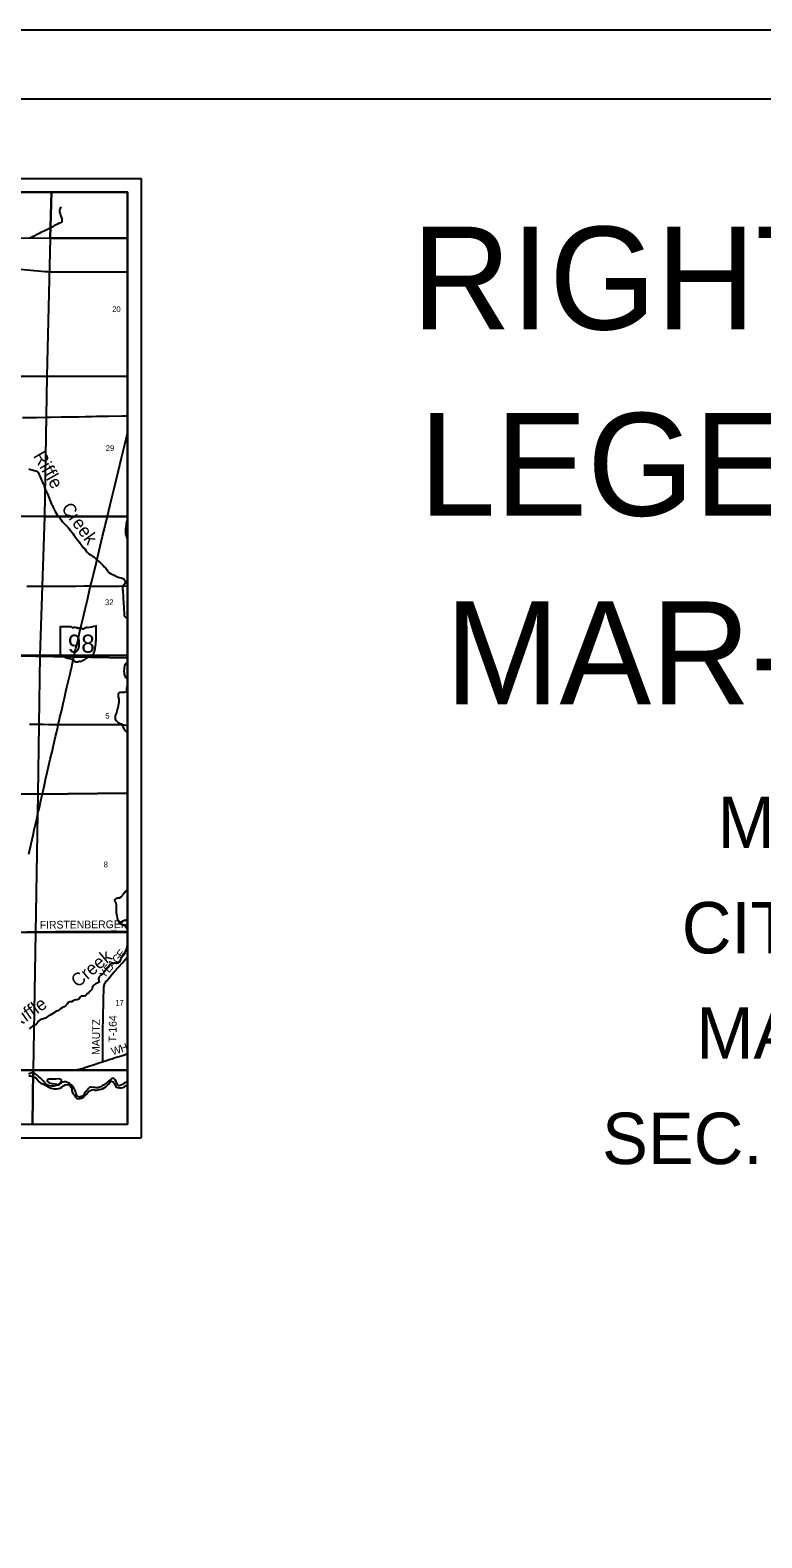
# Model space of a CAD drawing. Extents: x -97 to 34, y -21 to 22.
# Drawn here: x 9.64 to 14.98, y 11 to 22 of the extents above; entities that cross this region are included whole.
import ezdxf

# ---------------------------------------------------------------- set-up
doc = ezdxf.new("R2010")
doc.units = 0
for name, color, linetype in [('GM_X_County_Road', 7, 'Continuous'), ('GM_X_County_Road_Text', 7, 'Continuous'), ('GM_X_Major_River', 7, 'Continuous'), ('GM_X_Minor_River', 7, 'Continuous'), ('GM_X_Minor_River_Text', 7, 'Continuous'), ('GM_X_Section', 7, 'Continuous'), ('GM_X_Section_Text', 7, 'Continuous'), ('GM_X_State_Location', 7, 'Continuous'), ('GM_X_State_Route', 7, 'Continuous'), ('GM_X_State_Shield', 7, 'Continuous'), ('GM_X_Township', 7, 'Continuous'), ('GM_X_Township_Road', 7, 'Continuous'), ('GM_X_Township_Road_Text', 7, 'Continuous'), ('SH_Border', 7, 'Continuous'), ('SH_Cut_Line', 7, 'Continuous'), ('SH_Data', 7, 'Continuous'), ('SH_Text', 7, 'Continuous')]:
    doc.layers.add(name, color=color, linetype=linetype)

msp = doc.modelspace()

# ---------------------------------------------------------------- linework, layer by layer
at = {"layer": 'GM_X_County_Road'}
for points in [[(9.568, 20.257), (9.67, 20.247), (9.701, 20.244), (9.75, 20.24), (9.772, 20.238), (9.791, 20.237), (9.815, 20.237), (9.868, 20.237), (9.94, 20.237), (10.036, 20.237), (10.075, 20.237), (10.089, 20.237), (10.179, 20.237), (10.226, 20.237), (10.263, 20.237), (10.3, 20.237), (10.351, 20.236)], [(9.617, 17.943), (9.658, 17.943), (9.695, 17.943), (9.745, 17.943), (9.814, 17.943), (9.873, 17.944), (9.941, 17.944), (9.975, 17.944), (10.034, 17.945), (10.071, 17.945), (10.083, 17.945)], [(10.083, 17.945), (10.09, 17.944), (10.124, 17.944), (10.174, 17.944), (10.211, 17.944), (10.252, 17.944), (10.292, 17.944), (10.342, 17.945), (10.351, 17.945)], [(9.505, 15.42), (9.508, 15.42), (9.53, 15.42), (9.617, 15.421), (9.654, 15.421), (9.7, 15.421), (9.732, 15.422), (9.825, 15.423), (9.862, 15.423), (9.899, 15.423), (9.958, 15.424), (10.024, 15.424), (10.061, 15.425), (10.092, 15.425), (10.138, 15.425), (10.204, 15.425), (10.232, 15.426), (10.272, 15.426), (10.303, 15.425), (10.34, 15.425), (10.351, 15.425)], [(10.171, 14.474), (10.175, 14.476), (10.199, 14.483), (10.226, 14.492), (10.241, 14.496), (10.255, 14.501), (10.273, 14.506), (10.291, 14.511), (10.324, 14.521), (10.35, 14.531), (10.351, 14.532)], [(9.277, 14.411), (9.359, 14.41), (9.393, 14.409), (9.477, 14.41), (9.517, 14.411), (9.614, 14.411), (9.665, 14.412)], [(9.66, 14.018), (9.66, 14.037), (9.66, 14.062), (9.661, 14.087), (9.662, 14.161), (9.663, 14.192), (9.663, 14.22), (9.665, 14.257), (9.665, 14.269), (9.665, 14.285), (9.664, 14.32), (9.665, 14.354), (9.664, 14.362), (9.664, 14.367), (9.664, 14.369), (9.665, 14.377), (9.665, 14.387), (9.665, 14.397), (9.665, 14.408), (9.665, 14.412)], [(9.665, 14.412), (9.676, 14.412), (9.722, 14.412), (9.785, 14.413)], [(9.785, 14.413), (9.788, 14.413), (9.859, 14.413), (9.878, 14.414), (9.899, 14.414), (9.93, 14.415), (9.966, 14.415)], [(9.966, 14.415), (9.984, 14.417), (9.996, 14.418), (10.002, 14.419), (10.009, 14.421), (10.016, 14.423), (10.028, 14.426), (10.049, 14.433), (10.078, 14.443), (10.105, 14.452), (10.143, 14.465), (10.171, 14.474)]]:
    msp.add_lwpolyline(points, dxfattribs=at)
at = {"layer": 'GM_X_Major_River'}
for points in [[(9.841, 14.302), (9.824, 14.298), (9.812, 14.295), (9.799, 14.295), (9.786, 14.297), (9.776, 14.3), (9.764, 14.306), (9.75, 14.319), (9.737, 14.335), (9.726, 14.345), (9.716, 14.356), (9.705, 14.364), (9.692, 14.376), (9.678, 14.385), (9.668, 14.391), (9.655, 14.393), (9.643, 14.389), (9.629, 14.383)], [(9.632, 14.371), (9.645, 14.372), (9.66, 14.367), (9.673, 14.362), (9.685, 14.354), (9.696, 14.341), (9.708, 14.326), (9.721, 14.317), (9.735, 14.312), (9.748, 14.304), (9.76, 14.297), (9.771, 14.291), (9.782, 14.286), (9.796, 14.281), (9.806, 14.279), (9.816, 14.277), (9.837, 14.277), (9.852, 14.279), (9.861, 14.282), (9.874, 14.289), (9.884, 14.298), (9.897, 14.305), (9.91, 14.307), (9.923, 14.306), (9.935, 14.299), (9.942, 14.286), (9.945, 14.276), (9.946, 14.265), (9.948, 14.254), (9.954, 14.241), (9.963, 14.231), (9.972, 14.216), (9.982, 14.206), (9.995, 14.204), (10.006, 14.206), (10.017, 14.209), (10.031, 14.216), (10.043, 14.227), (10.052, 14.238), (10.062, 14.25), (10.071, 14.258), (10.081, 14.265), (10.092, 14.269), (10.103, 14.27), (10.116, 14.267), (10.126, 14.266), (10.138, 14.268), (10.148, 14.27), (10.16, 14.274), (10.17, 14.277), (10.183, 14.284), (10.193, 14.291), (10.206, 14.302), (10.218, 14.313), (10.225, 14.326), (10.235, 14.333), (10.247, 14.327), (10.256, 14.317), (10.262, 14.304), (10.267, 14.29), (10.28, 14.285), (10.293, 14.284), (10.306, 14.284), (10.319, 14.286), (10.331, 14.291), (10.343, 14.3), (10.351, 14.305)], [(9.851, 14.306), (9.851, 14.307), (9.852, 14.312), (9.856, 14.316), (9.863, 14.322), (9.867, 14.325), (9.871, 14.331), (9.871, 14.341), (9.863, 14.347), (9.848, 14.348), (9.83, 14.346), (9.81, 14.347), (9.792, 14.346), (9.777, 14.346), (9.768, 14.345), (9.766, 14.331), (9.781, 14.32), (9.801, 14.316), (9.823, 14.312), (9.834, 14.31), (9.839, 14.306), (9.841, 14.302)], [(9.841, 14.302), (9.851, 14.306)], [(9.851, 14.306), (9.841, 14.302)], [(10.351, 14.333), (10.344, 14.325), (10.328, 14.318), (10.316, 14.308), (10.303, 14.302), (10.292, 14.299), (10.282, 14.305), (10.276, 14.315), (10.27, 14.329), (10.262, 14.342), (10.251, 14.354), (10.238, 14.352), (10.226, 14.342), (10.213, 14.331), (10.203, 14.322), (10.178, 14.303), (10.167, 14.298), (10.157, 14.291), (10.147, 14.288), (10.137, 14.284), (10.124, 14.284), (10.113, 14.285), (10.088, 14.289), (10.077, 14.289), (10.067, 14.278), (10.061, 14.268), (10.051, 14.259), (10.038, 14.245), (10.033, 14.232), (10.023, 14.222), (10.013, 14.22), (10, 14.216), (9.987, 14.22), (9.982, 14.23), (9.978, 14.24), (9.975, 14.25), (9.971, 14.264), (9.964, 14.278), (9.956, 14.292), (9.944, 14.305), (9.929, 14.315), (9.915, 14.322), (9.901, 14.327), (9.891, 14.328), (9.881, 14.325), (9.869, 14.319), (9.851, 14.306)]]:
    msp.add_lwpolyline(points, dxfattribs=at)
at = {"layer": 'GM_X_Minor_River'}
for points in [[(9.866, 20.712), (9.861, 20.699), (9.857, 20.688), (9.857, 20.674), (9.86, 20.661), (9.864, 20.649), (9.872, 20.624), (9.874, 20.614), (9.874, 20.602), (9.864, 20.595), (9.854, 20.591), (9.842, 20.584), (9.828, 20.577), (9.813, 20.569), (9.802, 20.562), (9.789, 20.556), (9.764, 20.544), (9.755, 20.539), (9.743, 20.534), (9.731, 20.529), (9.72, 20.523), (9.707, 20.517), (9.697, 20.512), (9.681, 20.504), (9.67, 20.498), (9.655, 20.49), (9.64, 20.483)], [(9.633, 18.799), (9.644, 18.795), (9.656, 18.791), (9.67, 18.788), (9.684, 18.784), (9.695, 18.78), (9.702, 18.77), (9.708, 18.755), (9.714, 18.742), (9.721, 18.729), (9.725, 18.717), (9.73, 18.707)], [(9.73, 18.707), (9.735, 18.696), (9.741, 18.686), (9.745, 18.675), (9.747, 18.663), (9.751, 18.652), (9.756, 18.638), (9.763, 18.626), (9.768, 18.616), (9.773, 18.606), (9.778, 18.592), (9.784, 18.579), (9.789, 18.565), (9.793, 18.554), (9.798, 18.542), (9.804, 18.533), (9.81, 18.518), (9.817, 18.503), (9.825, 18.488), (9.832, 18.475), (9.839, 18.465), (9.848, 18.453), (9.858, 18.441), (9.868, 18.427), (9.876, 18.416), (9.892, 18.397), (9.909, 18.38), (9.919, 18.371), (9.929, 18.359), (9.936, 18.348), (9.946, 18.337), (9.955, 18.326), (9.964, 18.313), (9.971, 18.303), (9.977, 18.293), (9.985, 18.283), (9.996, 18.269), (10.004, 18.258), (10.011, 18.249), (10.02, 18.239), (10.032, 18.224), (10.04, 18.215), (10.047, 18.203), (10.059, 18.192), (10.071, 18.18), (10.081, 18.173), (10.096, 18.163), (10.106, 18.157), (10.116, 18.148), (10.132, 18.132), (10.142, 18.124), (10.154, 18.114), (10.165, 18.105), (10.175, 18.094), (10.182, 18.085), (10.192, 18.078), (10.201, 18.066), (10.207, 18.053), (10.217, 18.042), (10.229, 18.036), (10.239, 18.031), (10.254, 18.024), (10.267, 18.017), (10.283, 18.01), (10.294, 18.007), (10.305, 18.005), (10.318, 18), (10.328, 17.992), (10.334, 17.982), (10.337, 17.97), (10.331, 17.957), (10.32, 17.945), (10.316, 17.933), (10.316, 17.922), (10.319, 17.909), (10.319, 17.895), (10.32, 17.884), (10.32, 17.874), (10.32, 17.863), (10.321, 17.847), (10.322, 17.828), (10.324, 17.809), (10.325, 17.795), (10.326, 17.782), (10.326, 17.769), (10.327, 17.753), (10.328, 17.74), (10.329, 17.726), (10.337, 17.717), (10.351, 17.713), (10.351, 17.713)], [(10.351, 18.293), (10.346, 18.306), (10.343, 18.316), (10.341, 18.326), (10.34, 18.337), (10.34, 18.348), (10.341, 18.36), (10.342, 18.376), (10.344, 18.391), (10.346, 18.403), (10.35, 18.417), (10.351, 18.425)], [(10.335, 17.976), (10.343, 17.977), (10.351, 17.98)], [(10.351, 17.39), (10.345, 17.383), (10.336, 17.374), (10.33, 17.363), (10.327, 17.348), (10.327, 17.338), (10.326, 17.324), (10.327, 17.314), (10.328, 17.3), (10.333, 17.288), (10.341, 17.276), (10.351, 17.266)], [(10.351, 17.215), (10.347, 17.206), (10.345, 17.194), (10.344, 17.18), (10.341, 17.169), (10.328, 17.167), (10.314, 17.168), (10.304, 17.168), (10.295, 17.167), (10.285, 17.157), (10.284, 17.147), (10.285, 17.136), (10.289, 17.12), (10.289, 17.106), (10.288, 17.095), (10.286, 17.083), (10.283, 17.072), (10.281, 17.056), (10.277, 17.043), (10.274, 17.033), (10.271, 17.02), (10.266, 17.009), (10.262, 16.998), (10.261, 16.988), (10.262, 16.973), (10.273, 16.961), (10.285, 16.948), (10.298, 16.942), (10.309, 16.94), (10.316, 16.927), (10.317, 16.916), (10.326, 16.904), (10.336, 16.89), (10.345, 16.88), (10.351, 16.873)], [(10.351, 15.732), (10.351, 15.731), (10.339, 15.717), (10.331, 15.707), (10.32, 15.695), (10.313, 15.685), (10.304, 15.674), (10.291, 15.668), (10.281, 15.667), (10.27, 15.665), (10.258, 15.655), (10.26, 15.646), (10.267, 15.631), (10.27, 15.616), (10.27, 15.601), (10.27, 15.587), (10.27, 15.575), (10.269, 15.563), (10.272, 15.55), (10.275, 15.537), (10.276, 15.524), (10.278, 15.512), (10.286, 15.498), (10.295, 15.485)], [(10.292, 15.489), (10.304, 15.495), (10.314, 15.497), (10.326, 15.503), (10.338, 15.508), (10.348, 15.51), (10.351, 15.509)], [(10.295, 15.485), (10.309, 15.477), (10.323, 15.471), (10.337, 15.461), (10.348, 15.449), (10.351, 15.441)], [(10.351, 15.34), (10.35, 15.329), (10.347, 15.313), (10.344, 15.3), (10.34, 15.289), (10.336, 15.279), (10.33, 15.269), (10.319, 15.256), (10.313, 15.244), (10.305, 15.23), (10.3, 15.219), (10.296, 15.207), (10.292, 15.197), (10.282, 15.193), (10.272, 15.193), (10.261, 15.193), (10.251, 15.192), (10.239, 15.19), (10.229, 15.186), (10.215, 15.172), (10.203, 15.158), (10.194, 15.145), (10.187, 15.134), (10.178, 15.121), (10.167, 15.113), (10.157, 15.105), (10.146, 15.094), (10.14, 15.079), (10.144, 15.066), (10.145, 15.054), (10.132, 15.046), (10.119, 15.042), (10.107, 15.033), (10.096, 15.02), (10.094, 15.008), (10.089, 14.998), (10.078, 14.985), (10.068, 14.974), (10.057, 14.968), (10.045, 14.954), (10.035, 14.951), (10.025, 14.951), (10.014, 14.951), (10.003, 14.942), (9.996, 14.931), (9.985, 14.926), (9.976, 14.925), (9.965, 14.922), (9.955, 14.917), (9.943, 14.911), (9.931, 14.911), (9.919, 14.906), (9.911, 14.894), (9.903, 14.883), (9.889, 14.874), (9.878, 14.87), (9.865, 14.861), (9.855, 14.854), (9.843, 14.846), (9.833, 14.842), (9.823, 14.835), (9.813, 14.829), (9.8, 14.821), (9.789, 14.813), (9.774, 14.806), (9.765, 14.802), (9.754, 14.791), (9.739, 14.787), (9.726, 14.785), (9.715, 14.779), (9.702, 14.77), (9.693, 14.756), (9.683, 14.744), (9.669, 14.738), (9.658, 14.732), (9.647, 14.723), (9.635, 14.714)]]:
    msp.add_lwpolyline(points, dxfattribs=at)
at = {"layer": 'GM_X_Section'}
for p, q in [((9.797, 20.818), (8.644, 20.818)), ((10.351, 19.474), (10.351, 20.483)), ((10.351, 18.451), (10.351, 19.474)), ((10.351, 17.438), (10.351, 18.451)), ((10.351, 16.433), (10.351, 17.438)), ((10.351, 15.42), (10.351, 16.433)), ((10.351, 14.412), (10.351, 15.42)), ((8.554, 14.018), (9.658, 14.018))]:
    msp.add_line(p, q, dxfattribs=at)
for points in [[(8.644, 20.818), (8.639, 20.487), (9.789, 20.483), (9.797, 20.818)], [(9.797, 20.818), (9.789, 20.483), (10.351, 20.483)], [(10.351, 20.483), (10.351, 20.818), (9.797, 20.818)], [(10.351, 20.483), (9.789, 20.483), (9.763, 19.475), (10.351, 19.474)], [(10.351, 19.474), (9.763, 19.475), (9.747, 18.452), (10.351, 18.451)], [(10.351, 18.451), (9.747, 18.452), (9.712, 17.437), (10.351, 17.438)], [(10.351, 17.438), (9.712, 17.437), (9.697, 16.425), (10.351, 16.433)], [(10.351, 16.433), (9.697, 16.425), (9.681, 15.417), (10.351, 15.42)], [(10.351, 15.42), (9.681, 15.417), (9.665, 14.412), (10.351, 14.412)], [(9.658, 14.018), (9.665, 14.412), (8.557, 14.412), (8.554, 14.018)], [(9.658, 14.018), (10.351, 14.018), (10.351, 14.412)], [(10.351, 14.412), (9.665, 14.412), (9.658, 14.018)]]:
    msp.add_lwpolyline(points, dxfattribs=at)
for points in [[(9.789, 20.483), (9.763, 19.475), (8.63, 19.474), (8.63, 19.482), (8.638, 20.457), (8.639, 20.487)], [(9.763, 19.475), (9.747, 18.452), (8.617, 18.456), (8.63, 19.474)], [(9.747, 18.452), (9.712, 17.437), (8.604, 17.45), (8.617, 18.456)], [(9.712, 17.437), (9.697, 16.425), (8.584, 16.446), (8.604, 17.45)], [(8.584, 16.446), (9.697, 16.425), (9.681, 15.417), (8.566, 15.422), (8.566, 15.452)], [(8.566, 15.422), (9.681, 15.417), (9.665, 14.412), (8.557, 14.412), (8.557, 14.439)]]:
    msp.add_lwpolyline(points, close=True, dxfattribs=at)
at = {"layer": 'GM_X_State_Route'}
for points in [[(9.586, 19.174), (9.657, 19.175), (9.689, 19.175), (9.754, 19.176), (9.791, 19.177), (9.869, 19.178), (9.931, 19.179), (9.996, 19.18), (10.043, 19.181), (10.093, 19.182), (10.127, 19.183), (10.167, 19.183), (10.214, 19.184), (10.31, 19.186), (10.351, 19.186)], [(9.632, 15.989), (9.649, 16.064), (9.663, 16.126), (9.672, 16.165), (9.681, 16.204), (9.692, 16.256), (9.699, 16.286), (9.709, 16.329), (9.718, 16.368), (9.73, 16.42), (9.739, 16.459), (9.744, 16.482), (9.749, 16.505), (9.755, 16.532), (9.766, 16.584), (9.779, 16.638), (9.789, 16.68), (9.797, 16.717), (9.804, 16.744), (9.81, 16.771), (9.817, 16.802), (9.827, 16.847), (9.836, 16.883), (9.843, 16.914), (9.847, 16.934), (9.853, 16.96), (9.859, 16.988), (9.872, 17.039), (9.883, 17.088), (9.892, 17.127), (9.903, 17.175), (9.91, 17.206), (9.924, 17.266), (9.933, 17.303), (9.939, 17.327), (9.941, 17.336), (9.945, 17.354), (9.949, 17.372), (9.952, 17.384), (9.961, 17.424), (9.964, 17.435), (9.969, 17.46), (9.976, 17.49), (9.982, 17.514), (9.991, 17.554), (10.003, 17.602), (10.015, 17.654), (10.026, 17.702), (10.034, 17.735), (10.043, 17.775), (10.052, 17.814), (10.06, 17.844), (10.076, 17.914), (10.083, 17.945), (10.092, 17.98), (10.104, 18.029), (10.125, 18.119), (10.153, 18.234), (10.17, 18.307), (10.181, 18.355), (10.189, 18.385), (10.196, 18.412), (10.213, 18.485), (10.238, 18.588), (10.257, 18.666), (10.286, 18.787), (10.309, 18.88), (10.333, 18.977), (10.35, 19.05), (10.351, 19.054)], [(9.638, 16.937), (9.7, 16.936), (9.737, 16.936), (9.777, 16.935), (9.835, 16.935), (9.847, 16.934), (9.872, 16.934), (9.925, 16.934), (9.972, 16.934), (10.13, 16.935), (10.164, 16.935)], [(10.164, 16.935), (10.18, 16.935), (10.226, 16.935), (10.27, 16.935), (10.289, 16.934), (10.307, 16.933), (10.326, 16.931), (10.351, 16.928)]]:
    msp.add_lwpolyline(points, dxfattribs=at)
at = {"layer": 'GM_X_State_Shield'}
for p, q in [((9.861, 17.644), (9.861, 17.444)), ((9.94, 17.647), (9.863, 17.647)), ((10.124, 17.548), (10.124, 17.652)), ((10.124, 17.548), (10.124, 17.548))]:
    msp.add_line(p, q, dxfattribs=at)
for centre, radius, start, end in [((9.864, 17.644), 0.00305, 98.1301, 188.1301), ((9.959, 17.671), 0.0296, 231.6195, 271.1119), ((9.969, 17.535), 0.106, 80.4867, 94.9883), ((9.993, 17.645), 0.00855, 219.7921, 297.1024), ((10.005, 17.622), 0.0178, 54.4667, 119.1411), ((10.028, 17.654), 0.0214, 233.8562, 294.8282), ((10.066, 17.586), 0.0563, 97.3462, 120.7689), ((10.03, 17.92), 0.28, 275.8445, 288.9065), ((10.121, 17.653), 0.00294, 351.8621, 97.738), ((10.046, 17.49), 0.0699, 292.3089, 8.9858), ((10.135, 17.504), 0.0198, 136.8065, 186.9296), ((10.124, 17.54), 0.00454, 107.944, 210.337), ((10.095, 17.527), 0.0273, 340.033, 23.6496), ((10.121, 17.547), 0.00314, 289.6038, 7.7341), ((9.864, 17.443), 0.00308, 171.9584, 258.3066), ((9.864, 17.464), 0.0235, 267.339, 280.6039), ((9.869, 17.432), 0.00848, 29.7484, 93.2717), ((9.976, 17.612), 0.202, 240.4129, 257.1985), ((9.916, 17.354), 0.0632, 47.1842, 75.836), ((9.984, 17.431), 0.0401, 230.7004, 286.2918), ((10.007, 17.362), 0.0329, 85.6951, 111.2099), ((10.01, 17.416), 0.0214, 268.777, 315.5493), ((10.03, 17.397), 0.00601, 65.7517, 132.6484), ((10.027, 17.424), 0.0226, 282.8732, 323.2771), ((10.076, 17.388), 0.0383, 94.4031, 142.5768)]:
    msp.add_arc(centre, radius, start, end, dxfattribs=at)
at = {"layer": 'GM_X_Township'}
msp.add_lwpolyline([(10.351, 17.418), (8.605, 17.449)], dxfattribs=at)
at = {"layer": 'GM_X_Township_Road'}
msp.add_lwpolyline([(10.171, 14.474), (10.171, 14.477), (10.171, 14.492), (10.171, 14.511), (10.171, 14.555), (10.172, 14.583), (10.172, 14.62), (10.173, 14.654), (10.173, 14.688), (10.173, 14.719), (10.174, 14.778), (10.175, 14.834), (10.176, 14.881), (10.177, 14.943), (10.179, 14.993), (10.179, 15.008), (10.18, 15.018), (10.181, 15.024), (10.182, 15.03), (10.184, 15.036), (10.188, 15.044), (10.192, 15.052), (10.195, 15.058), (10.201, 15.065), (10.213, 15.079), (10.239, 15.11), (10.256, 15.129), (10.289, 15.166), (10.313, 15.194), (10.326, 15.208), (10.34, 15.225), (10.349, 15.237), (10.351, 15.24)], dxfattribs=at)
at = {"layer": 'SH_Border'}
msp.add_lwpolyline([(2, 21.5), (33.5, 21.5), (33.5, 0.5), (2, 0.5)], close=True, dxfattribs=at)
at = {"layer": 'SH_Cut_Line'}
msp.add_lwpolyline([(0, 0), (34, 0), (34, 22), (0, 22)], close=True, dxfattribs=at)
at = {"layer": 'SH_Data'}
for p, q in [((3.451, 20.918), (10.451, 20.918)), ((10.451, 20.918), (10.451, 13.918)), ((3.551, 20.818), (10.351, 20.818)), ((10.351, 20.818), (10.351, 14.018)), ((3.551, 14.018), (10.351, 14.018)), ((3.451, 13.918), (10.451, 13.918))]:
    msp.add_line(p, q, dxfattribs=at)

# ---------------------------------------------------------------- texts
at = {"layer": 'GM_X_County_Road_Text'}
for s, height, rotation, p in [('FIRSTENBERGER', 0.05682, 0.4287, (9.712, 15.444)), ('W', 0.0568, 17.6703, (10.244, 14.52)), ('H', 0.0568, 19.8201, (10.309, 14.54))]:
    msp.add_text(s, height=height, rotation=rotation, dxfattribs=at).set_placement(p)
at = {"layer": 'GM_X_Minor_River_Text'}
for s, rotation, p in [('Riffle', 300.0125, (9.661, 18.894)), ('Creek', 306.0121, (9.865, 18.511)), ('Creek', 40.0132, (9.989, 15.01)), ('Riffle', 35.0193, (9.537, 14.71))]:
    msp.add_text(s, height=0.0947, rotation=rotation, dxfattribs=at).set_placement(p)
at = {"layer": 'GM_X_Section_Text'}
for s, p in [('20', (10.24, 19.943)), ('29', (10.193, 18.93)), ('32', (10.188, 17.805)), ('5', (10.19, 16.977)), ('8', (10.178, 15.892)), ('17', (10.263, 14.883))]:
    msp.add_text(s, height=0.0419, rotation=0, dxfattribs=at).set_placement(p)
at = {"layer": 'GM_X_State_Location'}
msp.add_text('98', height=0.000189, rotation=0, dxfattribs=at).set_placement((9.942, 17.517))
for s in ['s', 'r']:
    msp.add_text(s, height=0.000189, dxfattribs=at).set_placement((9.99, 17.531))
at = {"layer": 'GM_X_State_Shield'}
msp.add_text('98', height=0.1318, dxfattribs=at).set_placement((9.917, 17.458))
at = {"layer": 'GM_X_Township_Road_Text'}
for s, rotation, p in [('E', 50.2683, (10.311, 15.226)), ('E', 48.9455, (10.216, 15.118)), ('A', 48.8977, (10.244, 15.15)), ('G', 48.9029, (10.277, 15.187)), ('Y', 50.3889, (10.184, 15.079)), ('MAUTZ', 89.2278, (10.149, 14.523)), ('T-164', 89.1657, (10.271, 14.614))]:
    msp.add_text(s, height=0.0568, rotation=rotation, dxfattribs=at).set_placement(p)
at = {"layer": 'SH_Text'}
for s, height, p in [('RIGHT OF WAY', 0.75, (12.427, 19.816)), ('LEGEND SHEET', 0.75, (12.48, 18.457)), ('MAR-423-07.40', 0.75, (12.669, 17.082)), ('     MARION COUNTY     ', 0.375, (13.961, 16.032)), ('   CITY OF MARION &    ', 0.375, (13.979, 15.264)), ('    MARION TOWNSHIP    ', 0.375, (13.945, 14.496)), ('SEC. 34, T. 5 S., R. 15 E.', 0.375, (13.815, 13.727))]:
    msp.add_text(s, height=height, dxfattribs=at).set_placement(p)

doc.saveas('drawing.dxf')
